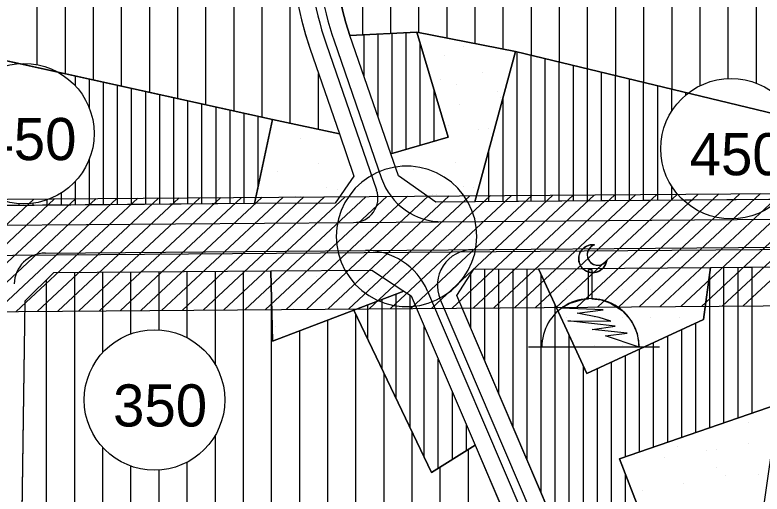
# Model space of a CAD drawing. Extents: x 419109 to 421295, y 4452223 to 4457798.
# Drawn here: x 420619.9 to 420885.6, y 4452782 to 4452952.7 of the extents above; entities that cross this region are included whole.
import ezdxf

# ---------------------------------------------------------------- set-up
doc = ezdxf.new("R2010")
doc.units = 0
for name, color, linetype in [('ADA', 7, 'Continuous'), ('ADAKENARI', 7, 'Continuous'), ('Default', 7, 'Continuous'), ('KALDIRIM', 7, 'Continuous'), ('KD_KAV_25', 7, 'Continuous'), ('LJ_SEMBOL', 7, 'Continuous'), ('PL_AYA_PARK_DINLENME', 7, 'Continuous'), ('PL_KON_MEV_350', 7, 'Continuous'), ('PL_KON_MEV_450', 7, 'Continuous'), ('PL_SAY_DINI_TESIS', 7, 'Continuous'), ('SM_DAIRE', 7, 'Continuous'), ('SM_TAKS', 7, 'Continuous'), ('TA_ENH_154', 7, 'Continuous'), ('TA_ENH_KORUMA', 7, 'Continuous'), ('TA_ENH_TARAMA', 7, 'Continuous'), ('TR_DINITESIS', 7, 'Continuous'), ('TR_ORTAYOGUNKONUT', 7, 'Continuous'), ('TR_PARKALANI', 7, 'Continuous'), ('TR_YUKSEKYOGUNKONUT', 7, 'Continuous')]:
    doc.layers.add(name, color=color, linetype=linetype)

# ---------------------------------------------------------------- blocks, each defined once
blk = doc.blocks.new('POINT_DISPLAY')
at = {"layer": 'Default'}
blk.add_line((0, 0), (0, 0), dxfattribs=at)

msp = doc.modelspace()

# ---------------------------------------------------------------- linework, layer by layer
at = {"layer": 'ADA'}
for p, q in [((420572.37, 4452946.15), (420711.55, 4452915.46)), ((420762.79, 4452946.51), (420739.04, 4452945.34)), ((420762.79, 4452946.51), (420797.89, 4452939.65)), ((420773.98, 4452909.13), (420762.79, 4452946.51)), ((420797.89, 4452939.65), (420783.48, 4452886.08)), ((420797.89, 4452939.65), (420896.71, 4452915.75)), ((420705.05, 4452885.46), (420711.55, 4452915.46)), ((420711.55, 4452915.46), (420735.28, 4452910.27)), ((420753.6, 4452903.15), (420773.98, 4452909.13)), ((420710.93, 4452861.51), (420711.48, 4452836.52)), ((420806.06, 4452862.26), (420823.32, 4452825)), ((420864.75, 4452844.21), (420867.3, 4452862.75)), ((420740.45, 4452847.57), (420758.23, 4452854.35)), ((420711.48, 4452836.52), (420740.45, 4452847.57)), ((420740.45, 4452847.57), (420768.05, 4452789.73)), ((420823.32, 4452825), (420864.75, 4452844.21)), ((420834.84, 4452794.55), (420891.35, 4452814.03)), ((420768.05, 4452789.73), (420783.53, 4452799.41)), ((420841.15, 4452778.37), (420834.84, 4452794.55))]:
    msp.add_line(p, q, dxfattribs=at)
at = {"layer": 'ADAKENARI'}
for p, q in [((420753.6, 4452903.15), (420739.04, 4452945.34)), ((420724.86, 4452940.44), (420735.28, 4452910.27)), ((420735.28, 4452910.27), (420740.47, 4452895.22)), ((420756.3, 4452895.35), (420753.6, 4452903.15)), ((420740.47, 4452895.22), (420733.73, 4452885.69)), ((420769.56, 4452885.97), (420756.3, 4452895.35)), ((421007.6, 4452887.86), (420783.48, 4452886.08)), ((420705.05, 4452885.46), (420569.34, 4452884.39)), ((420733.73, 4452885.69), (420705.05, 4452885.46)), ((420783.48, 4452886.08), (420769.56, 4452885.97)), ((420867.3, 4452862.75), (421075.71, 4452864.4)), ((420633.72, 4452860.9), (420710.93, 4452861.51)), ((420710.93, 4452861.51), (420746.86, 4452861.79)), ((420746.86, 4452861.79), (420758.23, 4452854.35)), ((420777.04, 4452852.8), (420783.11, 4452862.08)), ((420783.11, 4452862.08), (420806.06, 4452862.26)), ((420806.06, 4452862.26), (420867.3, 4452862.75)), ((420623.58, 4452850.82), (420633.72, 4452860.9)), ((420758.23, 4452854.35), (420760.78, 4452852.68)), ((420621.17, 4452683.2), (420623.58, 4452850.82)), ((420760.78, 4452852.68), (420783.53, 4452799.41)), ((420838.46, 4452709.01), (420777.04, 4452852.8)), ((420783.53, 4452799.41), (420807.35, 4452743.65))]:
    msp.add_line(p, q, dxfattribs=at)
for radius in [115, 100]:
    msp.add_arc((420833.57, 4452977.97), radius, 177.3972, 199.0423, dxfattribs=at)
at = {"layer": 'KALDIRIM'}
for p, q in [((420730.53, 4452942.4), (420748.51, 4452890.32)), ((420733.37, 4452943.38), (420750.26, 4452894.44)), ((420740.33, 4452878.74), (420914.42, 4452880.12)), ((420573.07, 4452877.42), (420740.33, 4452878.74)), ((420744.54, 4452868.77), (420915.46, 4452870.13)), ((420630.73, 4452867.87), (420744.54, 4452868.77)), ((420766.6, 4452854.33), (420846.56, 4452667.12)), ((420771.13, 4452851.37), (420849.32, 4452668.29))]:
    msp.add_line(p, q, dxfattribs=at)
for centre, radius, start, end in [((420833.57, 4452977.97), 109, 177.3972, 199.0423), ((420833.57, 4452977.97), 106, 177.3972, 199.0423), ((420771.93, 4452901.92), 22.92, 199.0423, 270.4539), ((420740.26, 4452887.47), 8.73, 270.4539, 19.0423), ((420782.83, 4452856.36), 12.72, 90.4539, 203.127), ((420630.82, 4452856.72), 11.16, 90.4539, 179.1769), ((420744.73, 4452844.99), 23.79, 23.127, 90.4539)]:
    msp.add_arc(centre, radius, start, end, dxfattribs=at)
at = {"layer": 'KD_KAV_25'}
for p, q in [((420754.49, 4452898.37), (420751.45, 4452897.59)), ((420757.61, 4452898.76), (420754.49, 4452898.37)), ((420760.75, 4452898.76), (420757.61, 4452898.76)), ((420763.86, 4452898.37), (420760.75, 4452898.76)), ((420766.9, 4452897.59), (420763.86, 4452898.37)), ((420748.53, 4452896.43), (420745.78, 4452894.92)), ((420751.45, 4452897.59), (420748.53, 4452896.43)), ((420769.82, 4452896.43), (420766.9, 4452897.59)), ((420772.57, 4452894.92), (420769.82, 4452896.43)), ((420743.24, 4452893.07), (420740.95, 4452890.93)), ((420745.78, 4452894.92), (420743.24, 4452893.07)), ((420775.11, 4452893.07), (420772.57, 4452894.92)), ((420777.4, 4452890.93), (420775.11, 4452893.07)), ((420740.95, 4452890.93), (420738.95, 4452888.51)), ((420779.4, 4452888.51), (420777.4, 4452890.93)), ((420738.95, 4452888.51), (420737.27, 4452885.86)), ((420781.09, 4452885.86), (420779.4, 4452888.51)), ((420737.27, 4452885.86), (420735.93, 4452883.01)), ((420782.42, 4452883.01), (420781.09, 4452885.86)), ((420735.93, 4452883.01), (420734.96, 4452880.03)), ((420783.39, 4452880.03), (420782.42, 4452883.01)), ((420734.96, 4452880.03), (420734.38, 4452876.95)), ((420783.98, 4452876.95), (420783.39, 4452880.03)), ((420734.38, 4452876.95), (420734.18, 4452873.81)), ((420784.18, 4452873.81), (420783.98, 4452876.95)), ((420734.18, 4452873.81), (420734.38, 4452870.68)), ((420783.98, 4452870.68), (420784.18, 4452873.81)), ((420734.38, 4452870.68), (420734.96, 4452867.59)), ((420783.39, 4452867.59), (420783.98, 4452870.68)), ((420734.96, 4452867.59), (420735.93, 4452864.61)), ((420782.42, 4452864.61), (420783.39, 4452867.59)), ((420735.93, 4452864.61), (420737.27, 4452861.77)), ((420781.09, 4452861.77), (420782.42, 4452864.61)), ((420737.27, 4452861.77), (420738.95, 4452859.12)), ((420779.4, 4452859.12), (420781.09, 4452861.77)), ((420738.95, 4452859.12), (420740.95, 4452856.7)), ((420777.4, 4452856.7), (420779.4, 4452859.12)), ((420740.95, 4452856.7), (420743.24, 4452854.55)), ((420775.11, 4452854.55), (420777.4, 4452856.7)), ((420743.24, 4452854.55), (420745.78, 4452852.7)), ((420772.57, 4452852.7), (420775.11, 4452854.55)), ((420745.78, 4452852.7), (420748.53, 4452851.19)), ((420748.53, 4452851.19), (420751.45, 4452850.04)), ((420766.9, 4452850.04), (420769.82, 4452851.19)), ((420769.82, 4452851.19), (420772.57, 4452852.7)), ((420751.45, 4452850.04), (420754.49, 4452849.25)), ((420754.49, 4452849.25), (420757.61, 4452848.86)), ((420757.61, 4452848.86), (420760.75, 4452848.86)), ((420760.75, 4452848.86), (420763.86, 4452849.25)), ((420763.86, 4452849.25), (420766.9, 4452850.04))]:
    msp.add_line(p, q, dxfattribs=at)
at = {"layer": 'LJ_SEMBOL'}
msp.add_line((420849.16, 4452834.31), (420802.5, 4452834.31), dxfattribs=at)
for points in [[(420830.33, 4452865.27), (420829.91, 4452863.76), (420829.04, 4452862.46), (420827.81, 4452861.49), (420826.34, 4452860.95), (420824.77, 4452860.89), (420823.27, 4452861.32), (420821.97, 4452862.19), (420821, 4452863.42), (420820.46, 4452864.89), (420820.41, 4452866.46), (420820.84, 4452867.97), (420821.71, 4452869.27), (420822.95, 4452870.23), (420824.42, 4452870.76), (420825.99, 4452870.81), (420824.74, 4452870.12), (420823.84, 4452869.01), (420823.42, 4452867.64), (420823.54, 4452866.21), (420824.2, 4452864.93), (420825.28, 4452863.99), (420826.63, 4452863.53), (420828.06, 4452863.61), (420829.36, 4452864.22)], [(420841.85, 4452834.32), (420829.87, 4452838.37), (420837.66, 4452839.29), (420825.22, 4452840.6), (420833.31, 4452841.86), (420816.56, 4452843.74), (420831.82, 4452843.67), (420827.65, 4452844.98), (420819.86, 4452846.42), (420829.09, 4452847.67), (420814.2, 4452848.19), (420817.36, 4452850.06), (420822.08, 4452851.45), (420823.83, 4452851.61), (420823.83, 4452862.03), (420825.08, 4452862.03), (420825.08, 4452851.62), (420828.32, 4452851.21), (420831.74, 4452850.06), (420835.88, 4452847.4), (420839.11, 4452843.68), (420841.15, 4452839.2)]]:
    msp.add_lwpolyline(points, close=True, dxfattribs=at)
for centre, radius, start, end in [((420825.37, 4452865.85), 5, 82.8556, 353.3219), ((420827.15, 4452867.25), 3.75, 107.9671, 328.2104), ((420824.55, 4452834.32), 17.31, 359.967, 180)]:
    msp.add_arc(centre, radius, start, end, dxfattribs=at)
at = {"layer": 'PL_AYA_PARK_DINLENME'}
for points in [[(420797.89, 4452939.65), (420783.48, 4452886.08), (420769.56, 4452885.97), (420756.3, 4452895.35), (420753.6, 4452903.15), (420773.98, 4452909.13), (420762.79, 4452946.51)], [(420705.05, 4452885.46), (420711.55, 4452915.46), (420735.28, 4452910.27), (420740.47, 4452895.22), (420733.73, 4452885.69)], [(420758.23, 4452854.35), (420740.45, 4452847.57), (420711.48, 4452836.52), (420710.93, 4452861.51), (420746.86, 4452861.79)], [(420885.32, 4452771.79), (420841.15, 4452778.37), (420834.84, 4452794.55), (420891.35, 4452814.03)]]:
    msp.add_lwpolyline(points, close=True, dxfattribs=at)
at = {"layer": 'PL_KON_MEV_350'}
msp.add_lwpolyline([(420720.65, 4452956.17), (420721.81, 4452950.86), (420723.21, 4452945.62), (420724.86, 4452940.44), (420735.28, 4452910.27), (420711.55, 4452915.46), (420572.37, 4452946.15), (420614.17, 4453144.54)], dxfattribs=at)
for points in [[(420853.73, 4453115.66), (420936.03, 4453098.7), (420930.77, 4453073.67), (420903.28, 4452943.11), (420896.71, 4452915.75), (420797.89, 4452939.65), (420762.79, 4452946.51), (420739.04, 4452945.34), (420737.61, 4452949.84), (420736.39, 4452954.4), (420735.38, 4452959.01), (420734.6, 4452963.67), (420734.03, 4452968.36), (420733.69, 4452973.07), (420733.57, 4452977.79), (420733.67, 4452982.51), (420778.66, 4453027.49), (420837.05, 4453013.96), (420840.26, 4453053.48), (420782.22, 4453058.47), (420778.66, 4453027.49), (420733.67, 4452982.51), (420739.7, 4453115.18), (420750.12, 4453124.34)], [(420798.57, 4452702.43), (420818.79, 4452638.95), (420784.82, 4452629.4), (420782.75, 4452656.88), (420722.16, 4452656.03), (420718.68, 4452691.01), (420711.53, 4452723.63), (420692.75, 4452768.31), (420648.07, 4452769.98), (420649.02, 4452720.06), (420711.53, 4452723.63), (420718.68, 4452691.01), (420621.17, 4452683.2), (420623.58, 4452850.82), (420633.72, 4452860.9), (420710.93, 4452861.51), (420711.48, 4452836.52), (420740.45, 4452847.57), (420768.05, 4452789.73), (420783.53, 4452799.41), (420807.35, 4452743.65), (420777.85, 4452729.81), (420780.7, 4452695.1)]]:
    msp.add_lwpolyline(points, close=True, dxfattribs=at)
at = {"layer": 'PL_KON_MEV_450'}
for points in [[(420705.05, 4452885.46), (420569.34, 4452884.39), (420561.41, 4452894.09), (420572.37, 4452946.15), (420711.55, 4452915.46)], [(420753.6, 4452903.15), (420739.04, 4452945.34), (420762.79, 4452946.51), (420773.98, 4452909.13)], [(421007.6, 4452887.86), (420783.48, 4452886.08), (420797.89, 4452939.65), (420896.71, 4452915.75), (420903.28, 4452943.11), (420937.46, 4452935.63), (421017.2, 4452936.24), (421017.52, 4452897.94)], [(421073.4, 4452859.66), (421049.81, 4452811.42), (421045.57, 4452802.75), (420918.87, 4452818.31), (420891.35, 4452814.03), (420834.84, 4452794.55), (420841.15, 4452778.37), (420885.32, 4452771.79), (420867.76, 4452703.68), (420838.46, 4452709.01), (420777.04, 4452852.8), (420783.11, 4452862.08), (420806.06, 4452862.26), (420823.32, 4452825), (420864.75, 4452844.21), (420867.3, 4452862.75), (421075.71, 4452864.4)], [(420768.05, 4452789.73), (420740.45, 4452847.57), (420758.23, 4452854.35), (420760.78, 4452852.68), (420783.53, 4452799.41)]]:
    msp.add_lwpolyline(points, close=True, dxfattribs=at)
at = {"layer": 'PL_SAY_DINI_TESIS'}
msp.add_lwpolyline([(420864.75, 4452844.21), (420823.32, 4452825), (420806.06, 4452862.26), (420867.3, 4452862.75)], close=True, dxfattribs=at)
at = {"layer": 'SM_DAIRE'}
for centre in [(420623.07, 4452910.41), (420874.57, 4452905.02), (420669.54, 4452815.56)]:
    msp.add_circle(centre, 25, dxfattribs=at)
at = {"layer": 'TA_ENH_154'}
msp.add_lwpolyline([(421244.23, 4452871.73), (420603.45, 4452866.93), (420104.11, 4452747.15), (419709.07, 4452649.72), (419353.3, 4452559.56), (419284.53, 4452601.29), (419287.68, 4452599.87), (419484.08, 4452691.72), (419833.95, 4454863.94), (419862.83, 4455014.24)], dxfattribs=at)
at = {"layer": 'TA_ENH_KORUMA'}
for points in [[(419883.15, 4455014.02), (419853.65, 4454860.46), (419502.14, 4452678.09), (419329.55, 4452597.37), (419356.51, 4452581.01), (419704.22, 4452669.12), (420099.38, 4452766.58), (420601.01, 4452886.92), (421244.44, 4452891.74)], [(421244.02, 4452851.67), (420605.55, 4452846.87), (420648.79, 4452887.27)]]:
    msp.add_lwpolyline(points, dxfattribs=at)
at = {"layer": 'TA_ENH_TARAMA'}
for p, q in [((420664.7, 4452847.39), (420707.85, 4452887.72)), ((420672.08, 4452847.44), (420715.23, 4452887.77)), ((420679.46, 4452847.5), (420722.62, 4452887.83)), ((420686.85, 4452847.55), (420730, 4452887.88)), ((420694.23, 4452847.61), (420737.38, 4452887.94)), ((420701.61, 4452847.66), (420744.76, 4452887.99)), ((420709, 4452847.72), (420752.15, 4452888.05)), ((420716.38, 4452847.78), (420759.53, 4452888.1)), ((420723.76, 4452847.83), (420766.91, 4452888.16)), ((420731.14, 4452847.89), (420774.29, 4452888.21)), ((420738.53, 4452847.94), (420781.68, 4452888.27)), ((420745.91, 4452848), (420789.06, 4452888.32)), ((420753.29, 4452848.05), (420796.44, 4452888.38)), ((420760.67, 4452848.11), (420803.83, 4452888.44)), ((420768.06, 4452848.16), (420811.21, 4452888.49)), ((420775.44, 4452848.22), (420818.59, 4452888.55)), ((420782.82, 4452848.27), (420825.97, 4452888.6)), ((420790.2, 4452848.33), (420833.36, 4452888.66)), ((420797.59, 4452848.38), (420840.74, 4452888.71)), ((420804.97, 4452848.44), (420848.12, 4452888.77)), ((420812.35, 4452848.49), (420855.5, 4452888.82)), ((420819.73, 4452848.55), (420862.89, 4452888.88)), ((420827.12, 4452848.61), (420870.27, 4452888.93)), ((420834.5, 4452848.66), (420877.65, 4452888.99)), ((420841.88, 4452848.72), (420885.03, 4452889.04)), ((420849.27, 4452848.77), (420892.42, 4452889.1)), ((420856.65, 4452848.83), (420899.8, 4452889.15)), ((420864.03, 4452848.88), (420907.18, 4452889.21)), ((420871.41, 4452848.94), (420914.56, 4452889.27)), ((420878.8, 4452848.99), (420921.95, 4452889.32)), ((420576, 4452839.78), (420626.64, 4452887.11)), ((420585.85, 4452842.14), (420634.02, 4452887.16)), ((420595.7, 4452844.5), (420641.41, 4452887.22)), ((420613.02, 4452847), (420656.17, 4452887.33)), ((420620.4, 4452847.06), (420663.55, 4452887.38)), ((420627.79, 4452847.11), (420670.94, 4452887.44)), ((420635.17, 4452847.17), (420678.32, 4452887.5)), ((420642.55, 4452847.22), (420685.7, 4452887.55)), ((420649.93, 4452847.28), (420693.09, 4452887.61)), ((420657.32, 4452847.33), (420700.47, 4452887.66))]:
    msp.add_line(p, q, dxfattribs=at)
at = {"layer": 'TR_ORTAYOGUNKONUT'}
for p, q in [((420677.83, 4452922.9), (420677.83, 4453358.21)), ((420687.83, 4452920.69), (420687.83, 4453348.49)), ((420627.83, 4452934.95), (420627.83, 4453275.8)), ((420637.83, 4452931.72), (420637.83, 4453262.35)), ((420667.83, 4452925.1), (420667.83, 4453263.99)), ((420647.83, 4452929.51), (420647.83, 4453258.43)), ((420657.83, 4452927.31), (420657.83, 4453258.88)), ((420697.83, 4452918.49), (420697.83, 4453178.54)), ((420707.83, 4452916.28), (420707.83, 4453178.27)), ((420717.83, 4452914.09), (420717.83, 4453177.99)), ((420753.57, 4452946.06), (420753.57, 4453124.05)), ((420763.57, 4452946.36), (420763.57, 4453123.21)), ((420773.57, 4452944.4), (420773.57, 4453122.37)), ((420743.57, 4452945.56), (420743.57, 4453118.58)), ((420783.57, 4452942.45), (420783.57, 4453026.35)), ((420793.57, 4452940.49), (420793.57, 4453024.03)), ((420803.57, 4452938.27), (420803.57, 4453021.72)), ((420813.57, 4452935.85), (420813.57, 4453019.4)), ((420823.57, 4452933.44), (420823.57, 4453017.08)), ((420833.57, 4452931.02), (420833.57, 4453014.77)), ((420883.57, 4452928.34), (420883.57, 4452978.63)), ((420843.57, 4452928.6), (420843.57, 4452962.39)), ((420873.57, 4452930), (420873.57, 4452962.01)), ((420853.57, 4452926.18), (420853.57, 4452957.76)), ((420863.57, 4452927.47), (420863.57, 4452957.65)), ((420727.83, 4452911.9), (420727.83, 4452931.84)), ((420661.17, 4452839.11), (420661.17, 4452861.11)), ((420671.17, 4452840.5), (420671.17, 4452861.19)), ((420681.17, 4452837.68), (420681.17, 4452861.27)), ((420691.17, 4452828.09), (420691.17, 4452861.35)), ((420701.17, 4452748.29), (420701.17, 4452861.43)), ((420641.17, 4452684.8), (420641.17, 4452860.96)), ((420651.17, 4452832.52), (420651.17, 4452861.03)), ((420631.17, 4452684), (420631.17, 4452858.36)), ((420711.17, 4452724.49), (420711.17, 4452850.73)), ((420741.17, 4452656.29), (420741.17, 4452846.07)), ((420731.17, 4452656.15), (420731.17, 4452844.03)), ((420721.17, 4452666.01), (420721.17, 4452840.21)), ((420751.17, 4452656.43), (420751.17, 4452825.11)), ((420691.17, 4452768.37), (420691.17, 4452803.03)), ((420761.17, 4452656.57), (420761.17, 4452804.15)), ((420651.17, 4452769.86), (420651.17, 4452798.6)), ((420781.17, 4452731.36), (420781.17, 4452797.94)), ((420681.17, 4452768.74), (420681.17, 4452793.43)), ((420661.17, 4452769.49), (420661.17, 4452792)), ((420671.17, 4452769.12), (420671.17, 4452790.61)), ((420771.17, 4452656.71), (420771.17, 4452791.69))]:
    msp.add_line(p, q, dxfattribs=at)
at = {"layer": 'TR_YUKSEKYOGUNKONUT'}
for p, q in [((420759.04, 4452904.75), (420759.04, 4452946.33)), ((420744.04, 4452930.85), (420744.04, 4452945.59)), ((420749.04, 4452916.37), (420749.04, 4452945.83)), ((420754.04, 4452903.28), (420754.04, 4452946.08)), ((420764.04, 4452906.21), (420764.04, 4452942.33)), ((420798.48, 4452886.2), (420798.48, 4452939.5)), ((420803.48, 4452886.24), (420803.48, 4452938.29)), ((420808.48, 4452886.28), (420808.48, 4452937.09)), ((420813.48, 4452886.32), (420813.48, 4452935.88)), ((420621.41, 4452935.34), (420621.41, 4452935.34)), ((420818.48, 4452886.36), (420818.48, 4452934.67)), ((420823.48, 4452886.4), (420823.48, 4452933.46)), ((420636.41, 4452931.55), (420636.41, 4452932.03)), ((420641.41, 4452927.4), (420641.41, 4452930.93)), ((420828.48, 4452886.44), (420828.48, 4452932.25)), ((420833.48, 4452886.48), (420833.48, 4452931.04)), ((420646.41, 4452919.38), (420646.41, 4452929.83)), ((420651.41, 4452885.04), (420651.41, 4452928.72)), ((420656.41, 4452885.08), (420656.41, 4452927.62)), ((420838.48, 4452886.52), (420838.48, 4452929.83)), ((420843.48, 4452886.56), (420843.48, 4452928.62)), ((420661.41, 4452885.12), (420661.41, 4452926.52)), ((420666.41, 4452885.16), (420666.41, 4452925.42)), ((420769.04, 4452907.68), (420769.04, 4452925.63)), ((420848.48, 4452886.6), (420848.48, 4452927.41)), ((420853.48, 4452918.44), (420853.48, 4452926.21)), ((420858.48, 4452924.15), (420858.48, 4452925)), ((420671.41, 4452885.2), (420671.41, 4452924.31)), ((420676.41, 4452885.24), (420676.41, 4452923.21)), ((420793.48, 4452886.16), (420793.48, 4452923.25)), ((420681.41, 4452885.28), (420681.41, 4452922.11)), ((420686.41, 4452885.31), (420686.41, 4452921.01)), ((420691.41, 4452885.35), (420691.41, 4452919.9)), ((420696.41, 4452885.39), (420696.41, 4452918.8)), ((420701.41, 4452885.43), (420701.41, 4452917.7)), ((420706.41, 4452891.71), (420706.41, 4452916.6)), ((420711.41, 4452914.82), (420711.41, 4452915.5)), ((420788.48, 4452886.12), (420788.48, 4452904.67)), ((420646.41, 4452885), (420646.41, 4452901.43)), ((420641.41, 4452884.96), (420641.41, 4452893.41)), ((420853.48, 4452886.64), (420853.48, 4452891.59)), ((420636.41, 4452884.92), (420636.41, 4452889.26)), ((420621.41, 4452884.8), (420621.41, 4452885.46)), ((420626.41, 4452884.84), (420626.41, 4452885.63)), ((420631.41, 4452884.88), (420631.41, 4452886.84)), ((420787.04, 4452829.39), (420787.04, 4452862.11)), ((420792.04, 4452817.68), (420792.04, 4452862.15)), ((420797.04, 4452805.98), (420797.04, 4452862.19)), ((420802.04, 4452794.27), (420802.04, 4452862.23)), ((420872.04, 4452807.37), (420872.04, 4452862.78)), ((420877.04, 4452809.1), (420877.04, 4452862.82)), ((420882.04, 4452810.82), (420882.04, 4452862.86)), ((420782.04, 4452841.1), (420782.04, 4452860.44)), ((420807.04, 4452782.56), (420807.04, 4452860.14)), ((420867.04, 4452805.65), (420867.04, 4452860.84)), ((420755.45, 4452816.13), (420755.45, 4452853.29)), ((420750.45, 4452826.61), (420750.45, 4452851.38)), ((420760.45, 4452805.65), (420760.45, 4452852.89)), ((420745.45, 4452837.09), (420745.45, 4452849.48)), ((420812.04, 4452770.86), (420812.04, 4452849.35)), ((420862.04, 4452803.93), (420862.04, 4452842.95)), ((420765.45, 4452795.16), (420765.45, 4452841.74)), ((420857.04, 4452802.2), (420857.04, 4452840.63)), ((420817.04, 4452759.15), (420817.04, 4452838.56)), ((420852.04, 4452800.48), (420852.04, 4452838.32)), ((420847.04, 4452798.76), (420847.04, 4452836)), ((420842.04, 4452797.03), (420842.04, 4452833.68)), ((420770.45, 4452791.24), (420770.45, 4452830.04)), ((420837.04, 4452795.31), (420837.04, 4452831.36)), ((420822.04, 4452747.44), (420822.04, 4452827.77)), ((420827.04, 4452735.73), (420827.04, 4452826.73)), ((420832.04, 4452724.03), (420832.04, 4452829.05)), ((420775.45, 4452794.36), (420775.45, 4452818.33)), ((420780.45, 4452797.49), (420780.45, 4452806.62)), ((420837.04, 4452712.32), (420837.04, 4452788.92))]:
    msp.add_line(p, q, dxfattribs=at)

# ---------------------------------------------------------------- block references
at = {"layer": 'TR_DINITESIS', "xscale": 0.1, "yscale": 0.10000000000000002}
for p in [(420816.06, 4452855), (420826.06, 4452855), (420836.06, 4452855), (420846.06, 4452855), (420856.06, 4452855), (420866.06, 4452855), (420816.06, 4452845), (420826.06, 4452845), (420836.06, 4452845), (420846.06, 4452845), (420856.06, 4452845), (420826.06, 4452835), (420836.06, 4452835)]:
    msp.add_blockref('POINT_DISPLAY', p, dxfattribs=at)
at = {"layer": 'TR_PARKALANI', "xscale": 0.1, "yscale": 0.10000000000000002}
for p in [(420779.39, 4452941.29), (420772.7, 4452938.36), (420786.05, 4452932.31), (420771.28, 4452929.71), (420776.85, 4452928.06), (420791.62, 4452925.46), (420792.71, 4452923.33), (420777.94, 4452920.73), (420774.24, 4452913.29), (420784.6, 4452911.75), (420788.15, 4452912.17), (420721.28, 4452908.63), (420788.15, 4452905.76), (420727.94, 4452899.65), (420776.49, 4452900.16), (420713.17, 4452897.05), (420761.71, 4452897.56), (420706.58, 4452890.77), (420730.71, 4452891.14), (420734.6, 4452890.67), (420736.99, 4452890.48), (420779.26, 4452891.65), (420783.15, 4452891.18), (420719.83, 4452888.07), (420721.35, 4452888.16), (420768.38, 4452888.58), (420769.9, 4452888.67), (420715.93, 4452861.52), (420727.15, 4452859.69), (420712.38, 4452857.08), (420745.47, 4452856.31), (420748.58, 4452853.31), (420733.81, 4452850.71), (420719.04, 4452848.1), (420712.46, 4452841.82), (420880.88, 4452807.62), (420880.61, 4452800.16), (420855.49, 4452799.11), (420865.84, 4452797.56), (420869.39, 4452797.98), (420851.07, 4452794.96), (420836.3, 4452792.35), (420869.39, 4452791.58), (420872.5, 4452788.58), (420884.16, 4452788.97), (420857.73, 4452785.98), (420842.96, 4452783.37)]:
    msp.add_blockref('POINT_DISPLAY', p, dxfattribs=at)

# ---------------------------------------------------------------- texts
at = {"layer": 'SM_TAKS'}
for s, p in [('450', (420608.33, 4452900.96)), ('450', (420859.83, 4452895.57)), ('350', (420654.79, 4452806.11))]:
    msp.add_text(s, height=15, dxfattribs=at).set_placement(p)

doc.saveas('drawing.dxf')
